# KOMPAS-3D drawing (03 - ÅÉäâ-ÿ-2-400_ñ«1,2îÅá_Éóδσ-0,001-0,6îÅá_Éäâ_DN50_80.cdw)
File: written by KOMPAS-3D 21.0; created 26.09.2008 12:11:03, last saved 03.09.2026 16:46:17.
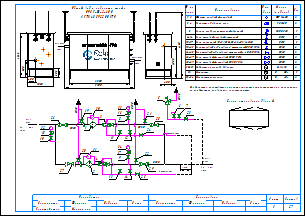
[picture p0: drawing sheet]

Sheets 1-2: A3, landscape

Document properties: Наименование: Макро:21; Автор: RaskoAdmin; Форматы листов документа: 2xA3; Полное имя файла: \\UR38nt01\Departments\КТО\КБ ПУРДГ\Заявки\Прайс-лист на типовые шкафы ГРПШ\ПРДГ_стандарт_20_03_2026\ПРДГ с РДГ(Н, В)\ПРДГ-Ш-2-400_до1,2МПа_Рвых-0,001-0,6МПа_РДГ_DN50_80.cdw

Title block, sheet 1: Наименование: Пункт учета газа / ПУГ-Ш-400-Р / ЛГТИ.485922.001ТУ; designation: ЛГТИ.03.4411141; sheet number: 1; Количество листов документа: 2; organisation: ООО "ЭЛЬСТЕР Газэлектроника"; Форматы листов документа: A3; stored path: C:\Рабочие документы\Компас\ПУГ\Схема.cdw; Разработал: Устинов; Проверил: Кошкин; Утвердил: Кошкин
Title block, sheet 2: sheet number: 2; stored path: D:\Рабочие документы\Заявки\ПУРДГ\ПУРДГ-ШУЭО-2-100-Р 4411220.cdw; designation, second copy: ЛГТИ.03.4411141-

Views: Вид 1, Вид 2
Referenced files: wcvoit.frw
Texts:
  Normal
  № на
  схеме
  Усл.
  обозн.
  Марка
  (модель)
  Кол.
  Фильтр газовый фланцевый
  ФГ 16-50
  Регулятор давления газа
  РДГ-50
  Клапан предохранительный сбросной
  КПС DN20
  Кран шаровой газовый латунный
  DN15
  Кран кнопочный VE-РАСКО-НЗ-1,6-G1/2-М20
  Кран шаровой "под приварку" штуцерный DN20 PN16
  Кран шаровой "под приварку" штуцерный п/п DN20 PN16
  DN20
  Кран шаровой фланцевый DN50 PN16
  Кран шаровой фланцевый DN80 PN16
  DN50
  DN80
  Индикатор перепада давления
  Delta 15
  Манометр
  Манометр-напоромер
  0...     МПа
  0...     кПа
  Общий вид и габариты шкафа
  ПРДГ-Ш-2-400
  Выход газа
  Вход газа
  logo-rasko-ge.png
  Вход
  газа
  PDI
  Выход
  Р=     кПа
  Импульс DN20
  ≥5DN
  HYSWLongFangSong
  Р=       МПа
  Схема открывания дверей
  Предприятие изготовитель может заменять комплектующие на аналогичные,
  не ухудшающие заявленных характеристик.
  Должность
  Конструктор
  Фамилия
  Подпись
  Дата
  Согласовано
  Максимкин
  Лист
  Листов
  POLYLINE_STYLE_0.18_RGB_0_0_0
  POLYLINE_STYLE_0.50_RGB_0_0_0
  POLYLINE_STYLE_0.34_RGB_0_0_0
  PHANTOM_RGB_0_0_0_SC_1_THICK_0.18
  K5LT_THIN_RGB_0_0_0_THICK_0.18
  K5LT32769_RGB_0_0_0_THICK_0.18
  K5LT12_RGB_0_0_0_SC_1_THICK_0.18
  K5LT_DASHED_RGB_0_0_0_SC_1_THICK_0.18
  ACISOTGL_RGB_0_0_0_SC_0.8_THICK_0.25
  CONTINUOUS_RGB_0_127_31_THICK_0.3
  CONTINUOUS_RGB_0_0_255_THICK_0.35
  CONTINUOUS_RGB_255_0_0_THICK_0.35
  POLYLINE_STYLE_0.25_RGB_0_0_0
  CONTINUOUS_RGB_0_0_0_THICK_0.5
  POLYLINE_STYLE_0.35_RGB_0_0_255
  CONTINUOUS_RGB_0_0_0_THICK_0.4
  CONTINUOUS_RGB_0_0_0_THICK_0.35
  Без оформления
Dimensions and other numbers on the sheet: 1; 1, 2; 2; 3, 4; 5; 6-14; 9; 15-17; 3; 18-23; 24-25; 6; 26-27; 28-29; 30-31; 32; 33-34; 400; 1050; 500; 305; 1565; 3100; 1000; 4130; 2800; 4; 10; 27; 28; 29; 23; 8; 12; 19; 20; 21; 22; 25; 24; 30; 31; 15; 16; 26; 7; 11; 14; 13; 33; 17; 34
